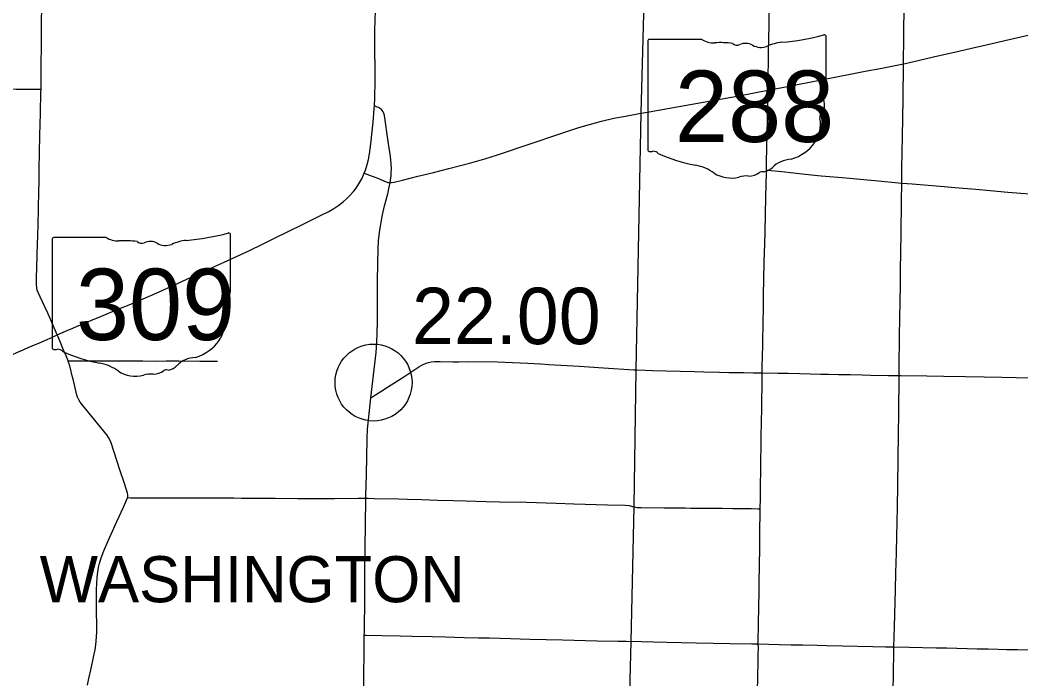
# Model space of a CAD drawing. Extents: x 9078 to 9739, y 4248 to 4966.
# Drawn here: x 9362.4 to 9460, y 4831.1 to 4895.4 of the extents above; entities that cross this region are included whole.
import ezdxf

# ---------------------------------------------------------------- set-up
doc = ezdxf.new("R2010")
doc.units = 0
for name, color, linetype in [('Default', 7, 'Continuous'), ('GM_X_County_Road', 7, 'Continuous'), ('GM_X_State_Route', 7, 'Continuous'), ('GM_X_State_Shield', 7, 'Continuous'), ('GM_X_Township', 7, 'Continuous'), ('GM_X_Township_Road', 7, 'Continuous'), ('GM_X_Township_Text', 7, 'Continuous')]:
    doc.layers.add(name, color=color, linetype=linetype)

msp = doc.modelspace()

# ---------------------------------------------------------------- linework, layer by layer
at = {"layer": 'Default'}
msp.add_circle((9396.845, 4860.027), 3.75, dxfattribs=at)
at = {"layer": 'GM_X_County_Road'}
for points in [[(9364.415, 4888.64), (9364.423, 4889.76), (9364.435, 4891.154), (9364.45, 4892.794), (9364.475, 4895.089), (9364.501, 4896.728), (9364.582, 4902.221), (9364.605, 4903.943), (9364.624, 4905.009), (9364.648, 4906.648), (9364.66, 4907.468), (9364.678, 4908.533), (9364.69, 4909.352), (9364.717, 4910.991), (9364.734, 4912.385), (9364.769, 4914.27), (9364.791, 4915.091), (9364.792, 4915.174), (9364.794, 4915.334)], [(9435.305, 4888.55), (9435.314, 4889.065), (9435.361, 4892.264), (9435.411, 4894.889), (9435.424, 4896.121), (9435.438, 4896.693), (9435.461, 4897.67), (9435.464, 4898.482), (9435.468, 4898.959), (9435.485, 4900.498), (9435.53, 4904.353), (9435.585, 4908.208), (9435.604, 4910.013), (9435.657, 4912.719), (9435.665, 4913.622), (9435.667, 4913.71)], [(9448.526, 4891.131), (9448.533, 4891.673), (9448.551, 4893.232), (9448.572, 4894.709), (9448.595, 4896.103), (9448.679, 4900.698), (9448.699, 4902.42), (9448.716, 4903.815), (9448.724, 4904.964), (9448.768, 4906.602), (9448.8, 4907.996), (9448.828, 4910.458), (9448.873, 4913.349)], [(9448.355, 4879.497), (9448.372, 4880.925), (9448.428, 4884.042), (9448.482, 4887.652), (9448.526, 4891.131)], [(9364.16, 4876.877), (9364.179, 4877.409), (9364.196, 4878.309), (9364.209, 4878.882), (9364.22, 4879.371), (9364.226, 4879.616), (9364.23, 4879.711), (9364.232, 4879.869), (9364.235, 4880.105), (9364.25, 4880.998), (9364.271, 4882.307), (9364.316, 4884.274), (9364.334, 4885.092), (9364.369, 4886.401), (9364.413, 4888.286), (9364.415, 4888.64)], [(9435.157, 4880.753), (9435.171, 4881.521), (9435.281, 4887.098), (9435.305, 4888.55)], [(9434.75, 4860.966), (9434.757, 4861.594), (9434.795, 4863.644), (9434.809, 4864.464), (9434.829, 4865.366), (9434.845, 4866.104), (9434.861, 4867.088), (9434.887, 4868.564), (9434.954, 4871.762), (9434.997, 4873.566), (9435.03, 4874.714), (9435.104, 4878.159), (9435.152, 4880.455), (9435.157, 4880.753)], [(9448.091, 4860.714), (9448.098, 4861.479), (9448.147, 4864.597), (9448.198, 4867.961), (9448.22, 4869.437), (9448.241, 4870.996), (9448.29, 4874.525), (9448.335, 4877.725), (9448.355, 4879.497)], [(9448.355, 4879.497), (9448.399, 4879.494), (9449.374, 4879.408), (9450.926, 4879.285), (9452.477, 4879.145), (9453.539, 4879.057), (9455.582, 4878.886), (9456.969, 4878.758), (9458.685, 4878.619), (9462.118, 4878.345), (9463.999, 4878.205), (9464.979, 4878.126), (9465.849, 4878.058)], [(9365.998, 4864.676), (9365.703, 4865.379), (9365.305, 4866.278), (9365.065, 4866.797), (9364.755, 4867.465), (9364.124, 4868.801), (9364.042, 4869.035), (9363.994, 4869.28), (9363.975, 4869.61), (9363.984, 4870.176), (9363.987, 4870.349), (9364.012, 4871.164), (9364.054, 4872.555), (9364.082, 4873.537), (9364.107, 4874.357), (9364.142, 4875.504), (9364.16, 4876.877)], [(9366.311, 4863.922), (9366.084, 4864.473), (9365.998, 4864.676)], [(9366.644, 4863.132), (9366.551, 4863.34), (9366.311, 4863.922)], [(9367.068, 4862.137), (9366.868, 4862.627), (9366.644, 4863.132)], [(9367.491, 4860.557), (9367.22, 4861.647), (9367.077, 4862.116), (9367.068, 4862.137)], [(9367.961, 4858.616), (9367.909, 4858.799), (9367.837, 4859.107), (9367.536, 4860.374), (9367.491, 4860.557)], [(9434.553, 4847.709), (9434.565, 4848.72), (9434.574, 4849.786), (9434.598, 4851.673), (9434.65, 4854.542), (9434.678, 4856.347), (9434.696, 4857.33), (9434.715, 4858.314), (9434.73, 4859.708), (9434.75, 4860.966)], [(9447.599, 4834.249), (9447.639, 4836.211), (9447.736, 4839.82), (9447.784, 4841.461), (9447.831, 4843.429), (9447.867, 4845.07), (9447.902, 4846.382), (9447.932, 4847.858), (9447.958, 4849.992), (9448.028, 4855.079), (9448.056, 4856.966), (9448.091, 4860.714)], [(9372.863, 4848.807), (9372.881, 4848.853), (9372.894, 4848.93), (9372.895, 4849.006), (9372.874, 4849.11), (9372.841, 4849.241), (9372.543, 4850.177), (9372.138, 4851.425), (9371.806, 4852.438), (9371.245, 4854.152), (9371.124, 4854.454), (9371.008, 4854.666), (9370.819, 4854.93), (9369.377, 4856.717), (9368.248, 4858.125), (9368.105, 4858.328), (9368.024, 4858.474), (9367.961, 4858.616)], [(9368.934, 4830.519), (9369.068, 4831.162), (9369.291, 4832.121), (9369.547, 4833.239), (9369.685, 4833.963), (9369.754, 4834.448), (9369.823, 4835.182), (9369.856, 4835.753), (9369.862, 4836.326), (9369.835, 4837.719), (9369.813, 4838.946), (9369.837, 4839.849), (9369.892, 4840.996), (9369.943, 4841.569), (9370.011, 4841.975), (9370.109, 4842.375), (9370.285, 4842.923), (9370.556, 4843.611), (9370.974, 4844.591), (9371.81, 4846.464), (9372.444, 4847.887), (9372.752, 4848.557), (9372.852, 4848.778), (9372.863, 4848.807)], [(9372.863, 4848.807), (9372.921, 4848.8), (9373.146, 4848.772), (9373.563, 4848.768), (9374.3, 4848.771), (9375.283, 4848.778), (9376.02, 4848.781), (9377.084, 4848.784), (9379.869, 4848.777), (9380.933, 4848.777), (9382.326, 4848.778), (9383.226, 4848.773), (9383.963, 4848.764), (9385.191, 4848.755), (9385.928, 4848.749), (9387.238, 4848.747), (9389.448, 4848.733), (9391.251, 4848.732), (9393.052, 4848.733), (9395.345, 4848.743), (9396.099, 4848.749)], [(9434.365, 4834.522), (9434.359, 4834.768), (9434.39, 4836.473), (9434.429, 4838.195), (9434.452, 4839.59), (9434.465, 4840.82), (9434.479, 4841.886), (9434.507, 4844.182), (9434.518, 4845.165), (9434.52, 4845.381), (9434.529, 4846.092), (9434.529, 4846.158), (9434.53, 4846.239), (9434.53, 4846.3), (9434.529, 4846.333), (9434.531, 4846.392), (9434.54, 4846.499), (9434.548, 4846.671), (9434.552, 4847.574), (9434.553, 4847.709)], [(9395.943, 4835.389), (9396.169, 4835.384), (9397.645, 4835.352), (9399.449, 4835.31), (9400.597, 4835.285), (9402.565, 4835.241), (9403.877, 4835.209), (9405.682, 4835.168), (9407.076, 4835.138), (9408.142, 4835.108), (9409.207, 4835.09), (9410.19, 4835.06), (9412.076, 4835.006), (9415.275, 4834.92), (9418.639, 4834.844), (9420.689, 4834.799), (9421.493, 4834.783)], [(9421.493, 4834.783), (9422.986, 4834.754), (9424.134, 4834.725), (9425.446, 4834.695), (9428.317, 4834.638), (9429.957, 4834.611), (9431.598, 4834.585), (9433.731, 4834.53), (9434.365, 4834.522)], [(9434.365, 4834.522), (9436.407, 4834.479), (9437.562, 4834.451), (9438.711, 4834.426), (9440.107, 4834.395), (9441.01, 4834.38), (9442.571, 4834.343), (9445.527, 4834.279), (9446.759, 4834.258), (9447.497, 4834.25), (9447.599, 4834.249)], [(9447.121, 4807.688), (9447.17, 4810.203), (9447.204, 4812.009), (9447.255, 4815.126), (9447.295, 4817.67), (9447.379, 4821.936), (9447.423, 4824.725), (9447.468, 4827.351), (9447.515, 4829.812), (9447.547, 4831.781), (9447.587, 4833.667), (9447.599, 4834.249)], [(9447.599, 4834.249), (9449.075, 4834.218), (9451.697, 4834.156), (9452.762, 4834.132), (9455.708, 4834.059), (9456.774, 4834.035), (9457.757, 4834.014), (9458.576, 4833.993), (9459.15, 4833.984), (9459.642, 4833.977), (9461.199, 4833.943), (9462.429, 4833.913), (9464.561, 4833.881), (9465.134, 4833.869), (9466.199, 4833.843), (9466.855, 4833.828), (9467.757, 4833.807), (9469.15, 4833.776), (9469.888, 4833.765), (9470.872, 4833.749), (9472.512, 4833.71), (9473.742, 4833.686)]]:
    msp.add_lwpolyline(points, dxfattribs=at)
at = {"layer": 'GM_X_State_Route'}
for points in [[(9396.922, 4887.013), (9396.96, 4887.793), (9397.011, 4889.434), (9397.014, 4890.419), (9396.984, 4892.715), (9396.975, 4894.273), (9396.987, 4895.503), (9397.025, 4896.157), (9397.094, 4896.725), (9397.214, 4897.368), (9397.459, 4898.405), (9397.976, 4900.389), (9398.349, 4901.817), (9398.808, 4903.562), (9399.437, 4905.985)], [(9398.451, 4879.52), (9398.511, 4879.519), (9398.594, 4879.531), (9398.87, 4879.586), (9399.667, 4879.775), (9401.177, 4880.153), (9402.69, 4880.528), (9404.201, 4880.907), (9406.344, 4881.47), (9407.686, 4881.845), (9408.935, 4882.247), (9412.123, 4883.321), (9415.001, 4884.289), (9416.872, 4884.905), (9417.894, 4885.212), (9419.085, 4885.527), (9420.284, 4885.806), (9421.411, 4886.031), (9422.913, 4886.3), (9423.35, 4886.379), (9427.713, 4887.15), (9432.317, 4887.975), (9435.305, 4888.55), (9435.862, 4888.658), (9440.533, 4889.566), (9444.802, 4890.396), (9446.252, 4890.674), (9448.526, 4891.131), (9448.986, 4891.225), (9451.465, 4891.793), (9453.624, 4892.289), (9455.462, 4892.719), (9457.301, 4893.141), (9458.823, 4893.481), (9461.94, 4894.201)], [(9382.266, 4871.764), (9383.413, 4872.287), (9384.752, 4872.911), (9386.003, 4873.527), (9387.107, 4874.069), (9389.974, 4875.488), (9391.669, 4876.318), (9392.473, 4876.73), (9392.971, 4877.017), (9393.45, 4877.337), (9393.909, 4877.684), (9394.22, 4877.954), (9394.568, 4878.304), (9394.892, 4878.676), (9395.14, 4879.004), (9395.411, 4879.417), (9395.699, 4879.916), (9395.877, 4880.288), (9395.941, 4880.454), (9396.054, 4880.749), (9396.224, 4881.299), (9396.343, 4881.778), (9396.448, 4882.344), (9396.581, 4883.32), (9396.805, 4885.442), (9396.902, 4886.745), (9396.922, 4887.013)], [(9398.451, 4879.52), (9398.5, 4879.811), (9398.547, 4880.157), (9398.575, 4880.473), (9398.586, 4880.87), (9398.57, 4881.36), (9398.495, 4882.092), (9398.285, 4883.553), (9397.909, 4886.067), (9397.848, 4886.301), (9397.781, 4886.445), (9397.69, 4886.576), (9397.608, 4886.663), (9397.517, 4886.733), (9397.426, 4886.79), (9397.312, 4886.849), (9397.182, 4886.908), (9396.922, 4887.013)], [(9395.941, 4880.454), (9396.176, 4880.364), (9397.325, 4879.922), (9397.859, 4879.712), (9398.24, 4879.562), (9398.311, 4879.541), (9398.394, 4879.524), (9398.451, 4879.52)], [(9395.889, 4829.798), (9395.943, 4835.389), (9395.946, 4835.703), (9395.989, 4839.065), (9396.003, 4841.279), (9396.036, 4844.067), (9396.064, 4846.118), (9396.099, 4848.749), (9396.102, 4848.988), (9396.143, 4851.038), (9396.217, 4854.563), (9396.262, 4855.465), (9396.37, 4856.691), (9396.586, 4858.552), (9397.084, 4862.964), (9397.17, 4863.943), (9397.211, 4864.843), (9397.23, 4865.991), (9397.24, 4868.205), (9397.245, 4869.927), (9397.256, 4871.649), (9397.289, 4873.042), (9397.341, 4873.861), (9397.427, 4874.677), (9397.546, 4875.489), (9397.718, 4876.376), (9397.925, 4877.255), (9398.234, 4878.445), (9398.404, 4879.247), (9398.451, 4879.52)], [(9369.282, 4866.087), (9370.303, 4866.51), (9371.21, 4866.898), (9371.642, 4867.067), (9372.176, 4867.281), (9373.014, 4867.623), (9374.374, 4868.195), (9375.653, 4868.754), (9377.295, 4869.502), (9378.637, 4870.118), (9380.434, 4870.923), (9381.7, 4871.506), (9382.266, 4871.764)], [(9356.688, 4860.469), (9358.27, 4861.244), (9358.584, 4861.395), (9359.083, 4861.635), (9359.608, 4861.872), (9360.728, 4862.377), (9361.629, 4862.769), (9362.345, 4863.081), (9362.382, 4863.098), (9363.153, 4863.434), (9363.948, 4863.78), (9364.036, 4863.818), (9365.012, 4864.244), (9365.614, 4864.505), (9365.998, 4864.676), (9366.813, 4865.038), (9367.508, 4865.34), (9367.866, 4865.495), (9368.428, 4865.733), (9368.542, 4865.781), (9368.823, 4865.897), (9369.036, 4865.985), (9369.282, 4866.087)]]:
    msp.add_lwpolyline(points, dxfattribs=at)
at = {"layer": 'GM_X_State_Shield'}
for p, q in [((9428.845, 4893.506), (9423.749, 4893.506)), ((9440.98, 4888.241), (9440.98, 4893.768)), ((9423.578, 4893.324), (9423.578, 4882.758)), ((9440.978, 4888.242), (9440.98, 4888.241)), ((9365.502, 4873.999), (9365.502, 4863.433)), ((9370.769, 4874.181), (9365.673, 4874.181)), ((9382.904, 4868.916), (9382.904, 4874.443)), ((9382.902, 4868.917), (9382.904, 4868.916))]:
    msp.add_line(p, q, dxfattribs=at)
for centre, major_axis, start_param, end_param in [((9423.777, 4893.347), (0.202, 0), 1.712693, 3.28349), ((9430.059, 4894.733), (1.955, 0), 4.042523, 4.731795), ((9434.781, 4907.912), (18.455, 0), 4.814394, 5.042369), ((9440.787, 4893.791), (0.194, 0), 6.141152, 7.989035), ((9430.707, 4887.574), (7.02, 0), 1.404758, 1.657858), ((9432.301, 4893.402), (0.564, 0), 3.836095, 5.185415), ((9433.129, 4892.18), (1.173, 0), 0.950623, 2.079405), ((9434.643, 4893.855), (1.411, 0), 4.081561, 5.145723), ((9437.135, 4890.279), (3.713, 0), 1.699011, 2.107814), ((9440.935, 4887.835), (0.3, 0), 1.883978, 3.671073), ((9439.028, 4887.136), (1.8, 0), 5.934695, 6.695948), ((9440.773, 4888.219), (0.207, 0), 5.05454, 6.418171), ((9441.674, 4885.928), (1.309, 0), 2.387724, 3.262537), ((9435.815, 4885.224), (4.616, 0), 5.101752, 6.440018), ((9423.779, 4882.735), (0.203, 0), 3.00124, 4.508301), ((9423.81, 4883.816), (1.552, 0), 4.665946, 4.897461), ((9424.127, 4882.148), (0.56, 0), 0.519207, 1.627899), ((9431.193, 4891.642), (13.327, 0), 4.195997, 4.488961), ((9437.761, 4879.792), (2.528, 0), 1.647645, 2.488434), ((9427.22, 4878.011), (4.17, 0), 0.823519, 1.323587), ((9434.558, 4881.734), (1.491, 0), 4.937069, 5.64225), ((9431.73, 4882.096), (2.646, 0), 4.026481, 4.996735), ((9433.259, 4878.443), (2.174, 0), 1.495662, 1.94098), ((9433.452, 4881.305), (1.41, 0), 4.691044, 5.507374), ((9434.727, 4880.281), (0.397, 0), 1.147584, 2.315152), ((9365.701, 4874.022), (0.202, 0), 1.712693, 3.28349), ((9371.983, 4875.408), (1.955, 0), 4.042523, 4.731795), ((9372.631, 4868.249), (7.02, 0), 1.404758, 1.657858), ((9379.059, 4870.954), (3.713, 0), 1.699011, 2.107814), ((9376.705, 4888.587), (18.455, 0), 4.814394, 5.042369), ((9382.711, 4874.466), (0.194, 0), 6.141152, 7.989035), ((9374.225, 4874.077), (0.564, 0), 3.836095, 5.185415), ((9375.053, 4872.855), (1.173, 0), 0.950623, 2.079405), ((9376.567, 4874.53), (1.411, 0), 4.081561, 5.145723), ((9382.859, 4868.51), (0.3, 0), 1.883978, 3.671073), ((9380.952, 4867.811), (1.8, 0), 5.934695, 6.695948), ((9382.697, 4868.894), (0.207, 0), 5.05454, 6.418171), ((9383.598, 4866.603), (1.309, 0), 2.387724, 3.262537), ((9377.739, 4865.899), (4.616, 0), 5.101752, 6.440018), ((9365.703, 4863.41), (0.203, 0), 3.00124, 4.508301), ((9365.734, 4864.491), (1.552, 0), 4.665946, 4.897461), ((9366.051, 4862.823), (0.56, 0), 0.519207, 1.627899), ((9373.117, 4872.317), (13.327, 0), 4.195997, 4.488961), ((9379.685, 4860.467), (2.528, 0), 1.647645, 2.488434), ((9369.144, 4858.686), (4.17, 0), 0.823519, 1.323587), ((9375.376, 4861.98), (1.41, 0), 4.691044, 5.507374), ((9376.651, 4860.956), (0.397, 0), 1.147584, 2.315152), ((9376.482, 4862.409), (1.491, 0), 4.937069, 5.64225), ((9373.654, 4862.771), (2.646, 0), 4.026481, 4.996735), ((9375.183, 4859.118), (2.174, 0), 1.495662, 1.94098)]:
    msp.add_ellipse(centre, major_axis=major_axis, ratio=0.8, start_param=start_param, end_param=end_param, dxfattribs=at)
at = {"layer": 'GM_X_Township'}
msp.add_lwpolyline([(9421.269, 4808.362), (9421.979, 4834.777), (9422.27, 4847.941), (9422.446, 4861.285), (9422.928, 4886.346), (9423.704, 4914.119), (9424.443, 4940.552)], dxfattribs=at)
at = {"layer": 'GM_X_Township_Road'}
for points in [[(9345.005, 4888.889), (9346.252, 4888.865), (9347.728, 4888.845), (9349.859, 4888.811), (9352.646, 4888.763), (9353.547, 4888.754), (9355.761, 4888.729), (9358.713, 4888.697), (9360.517, 4888.683), (9361.993, 4888.664), (9363.303, 4888.652), (9363.877, 4888.647), (9364.287, 4888.642), (9364.415, 4888.64)], [(9435.157, 4880.753), (9435.275, 4880.741), (9436.662, 4880.604), (9438.947, 4880.375), (9440.496, 4880.212), (9442.537, 4880.021), (9445.721, 4879.732), (9448.355, 4879.497)], [(9367.068, 4862.137), (9367.23, 4862.137), (9368.075, 4862.137)], [(9368.075, 4862.137), (9368.801, 4862.137)], [(9368.801, 4862.137), (9369.286, 4862.137), (9370.331, 4862.153), (9371.646, 4862.153), (9373.617, 4862.145), (9374.339, 4862.145), (9375.644, 4862.13), (9376.629, 4862.148), (9377.862, 4862.133), (9379.916, 4862.105), (9380.82, 4862.104), (9381.476, 4862.12), (9381.64, 4862.127)], [(9396.586, 4858.552), (9396.764, 4858.654), (9397.049, 4858.816), (9397.668, 4859.219), (9398.219, 4859.576), (9399.186, 4860.193), (9399.806, 4860.594), (9400.767, 4861.224), (9400.968, 4861.375), (9401.247, 4861.553), (9401.608, 4861.747), (9401.982, 4861.907), (9402.216, 4861.982), (9402.457, 4862.034), (9402.783, 4862.069), (9403.357, 4862.076), (9404.588, 4862.066), (9405.162, 4862.064), (9406.063, 4862.069), (9408.935, 4862.051), (9410.411, 4862.001), (9411.886, 4861.915), (9413.114, 4861.841), (9413.932, 4861.784), (9416.881, 4861.612), (9419.256, 4861.462), (9422.225, 4861.278)], [(9422.225, 4861.278), (9422.515, 4861.268)], [(9422.515, 4861.268), (9423.319, 4861.239), (9424.054, 4861.209), (9425.362, 4861.171), (9428.142, 4861.092), (9429.042, 4861.072), (9430.595, 4861.036), (9431.495, 4861.019), (9432.967, 4860.996), (9433.905, 4860.973), (9434.75, 4860.966)], [(9434.75, 4860.966), (9436.294, 4860.948), (9437.278, 4860.933), (9438.426, 4860.9), (9439.41, 4860.875), (9440.477, 4860.851), (9441.215, 4860.841), (9442.199, 4860.829), (9443.348, 4860.802), (9444.496, 4860.78), (9445.316, 4860.762), (9447.039, 4860.732), (9448.091, 4860.714)], [(9448.091, 4860.714), (9448.269, 4860.709), (9450.813, 4860.682), (9452.453, 4860.648), (9454.586, 4860.604), (9456.391, 4860.579), (9458.113, 4860.555), (9459.508, 4860.537), (9462.954, 4860.476), (9465.661, 4860.431), (9467.92, 4860.4), (9468.944, 4860.385), (9470.092, 4860.354), (9472.298, 4860.318), (9472.79, 4860.312), (9473.528, 4860.295), (9474.089, 4860.278)], [(9396.099, 4848.749), (9396.335, 4848.744), (9396.909, 4848.732), (9399.291, 4848.679), (9400.111, 4848.647), (9401.506, 4848.607), (9403.066, 4848.566), (9404.624, 4848.52), (9405.856, 4848.487), (9407.826, 4848.431), (9409.139, 4848.405), (9411.766, 4848.346), (9414.641, 4848.269), (9416.364, 4848.207), (9419.649, 4848.106), (9421.373, 4848.057), (9421.778, 4848.025), (9421.861, 4848.011)], [(9421.861, 4848.011), (9422.217, 4847.913)], [(9422.217, 4847.913), (9422.304, 4847.889), (9422.547, 4847.852), (9422.956, 4847.832), (9425.17, 4847.813), (9427.22, 4847.792), (9427.793, 4847.785), (9428.776, 4847.785), (9429.514, 4847.78), (9430.826, 4847.768), (9431.891, 4847.756), (9433.121, 4847.746), (9433.695, 4847.731), (9434.35, 4847.71), (9434.432, 4847.71), (9434.553, 4847.709)], [(9433.923, 4807.984), (9433.926, 4808.129), (9433.944, 4808.782), (9433.965, 4809.763), (9433.984, 4810.91), (9434.034, 4813.368), (9434.057, 4814.924), (9434.096, 4817.298), (9434.13, 4819.262), (9434.147, 4820.164), (9434.14, 4823.483), (9434.157, 4824.059), (9434.212, 4824.779), (9434.238, 4825.929), (9434.26, 4827.485), (9434.283, 4828.55), (9434.297, 4829.615), (9434.328, 4831.58), (9434.35, 4832.563), (9434.365, 4833.545), (9434.371, 4834.119), (9434.365, 4834.522)]]:
    msp.add_lwpolyline(points, dxfattribs=at)

# ---------------------------------------------------------------- texts
at = {"layer": 'Default'}
msp.add_text('22.00', height=5.5, dxfattribs=at).set_placement((9400.595, 4863.777))
at = {"layer": 'GM_X_State_Shield'}
for s, p in [('288', (9426.235, 4883.503)), ('309', (9367.822, 4864.178))]:
    msp.add_text(s, height=6.961, dxfattribs=at).set_placement(p)
at = {"layer": 'GM_X_Township_Text'}
msp.add_text('WASHINGTON', height=4.5, rotation=0.00001, dxfattribs=at).set_placement((9364.29, 4838.593))

doc.saveas('drawing.dxf')
